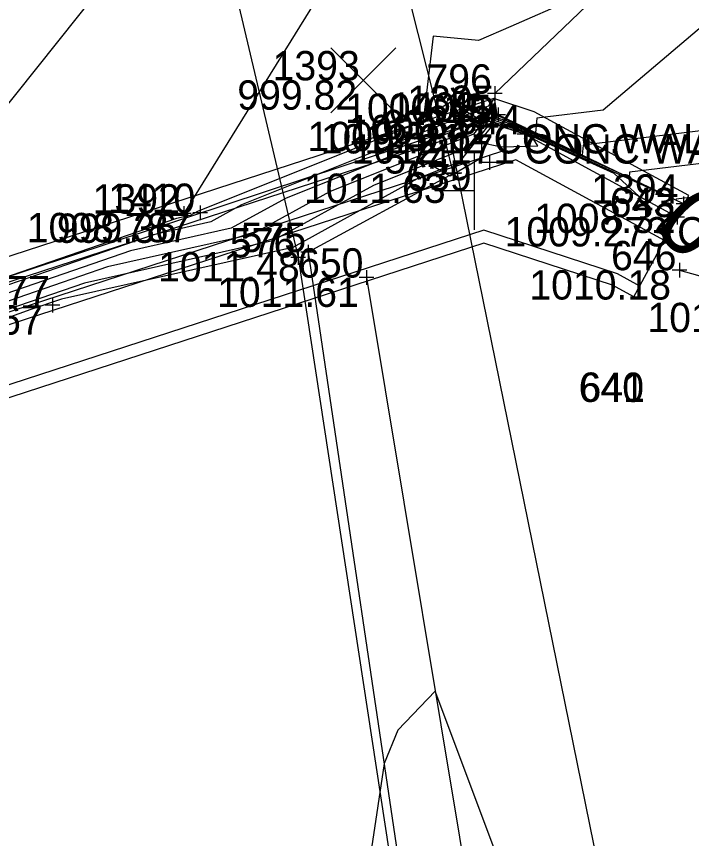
# Model space of a CAD drawing. Extents: x 2354693 to 2355622, y 637071 to 710080.
# Drawn here: x 2355356.22 to 2355383.87, y 709248.7 to 709282.34 of the extents above; entities that cross this region are included whole.
import ezdxf

# ---------------------------------------------------------------- set-up
doc = ezdxf.new("R2010")
doc.units = 0
for name, color, linetype in [('BR_X_Sub_Foot_Object', 7, 'Continuous'), ('BR_X_SV_Abut', 7, 'Continuous'), ('BR_X_SV_Beam_Seat', 7, 'Continuous'), ('DT_X_Contour_Major', 7, 'Continuous'), ('DT_X_Contour_Minor', 7, 'Continuous'), ('HY_X_Water_Edge', 7, 'Continuous'), ('PM_X_Surveyed_Line', 7, 'Continuous'), ('PV_X_EOP', 7, 'Continuous'), ('PV_X_Shoulder', 7, 'Continuous'), ('RD_X_Cells', 7, 'Continuous'), ('RD_X_GR_Lt', 7, 'Continuous'), ('SN_X_Public', 7, 'Continuous'), ('SV_X_Break_Lines', 7, 'Continuous'), ('SV_X_Random_Point', 7, 'Continuous'), ('SV_X_Shot_Marker', 7, 'Continuous'), ('SV_X_Text_Comment', 7, 'Continuous'), ('SV_X_Text_Elevation', 7, 'Continuous'), ('SV_X_Text_Name', 7, 'Continuous'), ('SV_X_Toe_of_Slope', 7, 'Continuous'), ('SV_X_Top_of_Bank', 7, 'Continuous')]:
    doc.layers.add(name, color=color, linetype=linetype)

msp = doc.modelspace()

# ---------------------------------------------------------------- linework, layer by layer
at = {"layer": 'BR_X_Sub_Foot_Object'}
for p, q in [((2355375.767, 709278.982), (2355343.344, 709268.433)), ((2355381.509, 709270.866), (2355383.755, 709275.004)), ((2355375.36, 709273.591), (2355346.408, 709264.172)), ((2355375.359, 709273.065), (2355346.73, 709263.751))]:
    msp.add_line(p, q, dxfattribs=at)
for points in [[(2355383.755, 709275.004), (2355377.429, 709278.438), (2355375.767, 709278.982)], [(2355381.747, 709271.305), (2355380.834, 709271.801), (2355375.36, 709273.591)], [(2355381.509, 709270.866), (2355380.635, 709271.34), (2355375.359, 709273.065)]]:
    msp.add_lwpolyline(points, dxfattribs=at)
at = {"layer": 'BR_X_SV_Abut'}
for p, q in [((2355375.766, 709277.93), (2355344.12, 709267.634)), ((2355376.127, 709276.82), (2355344.481, 709266.525)), ((2355376.68, 709276.474), (2355344.77, 709266.093))]:
    msp.add_line(p, q, dxfattribs=at)
for points in [[(2355383.278, 709274.125), (2355377.032, 709277.516), (2355375.766, 709277.93)], [(2355382.761, 709273.173), (2355376.68, 709276.474)]]:
    msp.add_lwpolyline(points, dxfattribs=at)
at = {"layer": 'BR_X_SV_Beam_Seat'}
for p, q in [((2355375.251, 709278.326), (2355375.251, 709277.726)), ((2355375.551, 709278.026), (2355374.951, 709278.026)), ((2355363.742, 709274.598), (2355363.742, 709273.998)), ((2355364.042, 709274.298), (2355363.442, 709274.298))]:
    msp.add_line(p, q, dxfattribs=at)
at = {"layer": 'DT_X_Contour_Major'}
for points in [[(2355412.935, 709323.858), (2355412.448, 709323.101), (2355399.508, 709300.34), (2355398.693, 709299.31), (2355397.28, 709297.832), (2355380.065, 709283.245), (2355378.962, 709283.026), (2355376.473, 709281.93), (2355375.148, 709281.346), (2355373.286, 709281.525), (2355372.881, 709278.048), (2355363.645, 709274.356), (2355363.341, 709274.189), (2355362.774, 709274.062), (2355345.265, 709268.035), (2355344.363, 709267.712), (2355344.138, 709267.795), (2355344.093, 709267.669), (2355343.399, 709266.464), (2355342.314, 709266.059), (2355339.268, 709265.779)], [(2355412.935, 709323.858), (2355412.448, 709323.101), (2355399.508, 709300.34), (2355398.693, 709299.31), (2355397.28, 709297.832), (2355380.065, 709283.245), (2355378.962, 709283.026), (2355376.473, 709281.93), (2355375.148, 709281.346), (2355373.286, 709281.525), (2355372.881, 709278.048), (2355363.645, 709274.356), (2355363.341, 709274.189), (2355362.774, 709274.062), (2355345.265, 709268.035), (2355344.363, 709267.712), (2355344.138, 709267.795), (2355344.093, 709267.669), (2355343.399, 709266.464), (2355342.314, 709266.059), (2355339.268, 709265.779)], [(2355382.151, 709274.282), (2355381.711, 709274.976), (2355380.703, 709275.914), (2355376.833, 709277.662), (2355375.801, 709278.001), (2355375.775, 709278.159), (2355374.352, 709276.373), (2355372.639, 709275.689), (2355367.547, 709272.887), (2355358.064, 709270.769), (2355356.817, 709270.34), (2355349.492, 709267.71), (2355349.176, 709262.706), (2355350.806, 709240.105), (2355350.736, 709238.617), (2355350.394, 709234.495), (2355350.966, 709223.924), (2355350.775, 709220.637), (2355349.098, 709206.498), (2355348.523, 709204.444)], [(2355382.151, 709274.282), (2355381.711, 709274.976), (2355380.703, 709275.914), (2355376.833, 709277.662), (2355375.801, 709278.001), (2355375.775, 709278.159), (2355374.352, 709276.373), (2355372.639, 709275.689), (2355367.547, 709272.887), (2355358.064, 709270.769), (2355356.817, 709270.34), (2355349.492, 709267.71), (2355349.176, 709262.706), (2355350.806, 709240.105), (2355350.736, 709238.617), (2355350.394, 709234.495), (2355350.966, 709223.924), (2355350.775, 709220.637), (2355349.098, 709206.498), (2355348.523, 709204.444)]]:
    msp.add_lwpolyline(points, dxfattribs=at)
at = {"layer": 'DT_X_Contour_Minor'}
for points in [[(2355395.378, 709291.328), (2355380.244, 709278.504), (2355377.533, 709278.175), (2355377.476, 709277.579), (2355376.098, 709278.202), (2355375.927, 709278.258), (2355375.806, 709278.989), (2355375.543, 709278.66), (2355365.444, 709274.623), (2355364.182, 709273.928), (2355361.832, 709273.404), (2355347.575, 709268.496), (2355344.823, 709267.508), (2355344.134, 709267.763), (2355343.996, 709267.379), (2355341.88, 709263.698), (2355341.299, 709263.481), (2355330.832, 709262.519), (2355327.686, 709262.765), (2355325.646, 709262.822), (2355317.774, 709259.038)], [(2355395.378, 709291.328), (2355380.244, 709278.504), (2355377.533, 709278.175), (2355377.476, 709277.579), (2355376.098, 709278.202), (2355375.927, 709278.258), (2355375.806, 709278.989), (2355375.543, 709278.66), (2355365.444, 709274.623), (2355364.182, 709273.928), (2355361.832, 709273.404), (2355347.575, 709268.496), (2355344.823, 709267.508), (2355344.134, 709267.763), (2355343.996, 709267.379), (2355341.88, 709263.698), (2355341.299, 709263.481), (2355330.832, 709262.519), (2355327.686, 709262.765), (2355325.646, 709262.822), (2355317.774, 709259.038)], [(2355403.537, 709290.84), (2355391.576, 709278.322), (2355390.037, 709277.018), (2355381.334, 709275.961), (2355381.313, 709275.742), (2355376.465, 709277.932), (2355375.864, 709278.129), (2355375.79, 709278.574), (2355374.947, 709277.517), (2355369.041, 709275.156), (2355365.864, 709273.408), (2355359.948, 709272.086), (2355352.196, 709269.418), (2355345.743, 709267.101), (2355344.127, 709267.698), (2355343.804, 709266.798), (2355341.172, 709262.22), (2355340.042, 709259.574), (2355339.274, 709259.634), (2355334.287, 709259.774), (2355315.044, 709250.525)], [(2355403.537, 709290.84), (2355391.576, 709278.322), (2355390.037, 709277.018), (2355381.334, 709275.961), (2355381.313, 709275.742), (2355376.465, 709277.932), (2355375.864, 709278.129), (2355375.79, 709278.574), (2355374.947, 709277.517), (2355369.041, 709275.156), (2355365.864, 709273.408), (2355359.948, 709272.086), (2355352.196, 709269.418), (2355345.743, 709267.101), (2355344.127, 709267.698), (2355343.804, 709266.798), (2355341.172, 709262.22), (2355340.042, 709259.574), (2355339.274, 709259.634), (2355334.287, 709259.774), (2355315.044, 709250.525)], [(2355393.477, 709284.825), (2355385.14, 709277.761), (2355379.434, 709277.068), (2355379.395, 709276.661), (2355376.282, 709278.067), (2355375.896, 709278.193), (2355375.798, 709278.782), (2355375.245, 709278.088), (2355367.243, 709274.889), (2355365.023, 709273.668), (2355360.89, 709272.745), (2355349.886, 709268.957), (2355345.283, 709267.305), (2355344.131, 709267.73), (2355343.9, 709267.089), (2355340.361, 709260.932), (2355340.284, 709260.903), (2355338.897, 709260.776), (2355333.48, 709261.199), (2355329.967, 709261.298), (2355316.409, 709254.782)], [(2355393.477, 709284.825), (2355385.14, 709277.761), (2355379.434, 709277.068), (2355379.395, 709276.661), (2355376.282, 709278.067), (2355375.896, 709278.193), (2355375.798, 709278.782), (2355375.245, 709278.088), (2355367.243, 709274.889), (2355365.023, 709273.668), (2355360.89, 709272.745), (2355349.886, 709268.957), (2355345.283, 709267.305), (2355344.131, 709267.73), (2355343.9, 709267.089), (2355340.361, 709260.932), (2355340.284, 709260.903), (2355338.897, 709260.776), (2355333.48, 709261.199), (2355329.967, 709261.298), (2355316.409, 709254.782)], [(2355384.85, 709275.05), (2355383.235, 709274.854), (2355383.232, 709274.823), (2355376.649, 709277.797), (2355375.833, 709278.065), (2355375.782, 709278.367), (2355374.649, 709276.945), (2355370.84, 709275.422), (2355366.705, 709273.148), (2355359.006, 709271.428), (2355354.506, 709269.879), (2355346.203, 709266.898), (2355344.124, 709267.666), (2355343.708, 709266.508), (2355342.404, 709264.24), (2355341.712, 709262.62), (2355342.07, 709261.383), (2355340.341, 709258.201), (2355338.608, 709258.25), (2355328.095, 709253.197), (2355324.733, 709239.533), (2355325.082, 709235.631), (2355314.187, 709221.342)], [(2355384.85, 709275.05), (2355383.235, 709274.854), (2355383.232, 709274.823), (2355376.649, 709277.797), (2355375.833, 709278.065), (2355375.782, 709278.367), (2355374.649, 709276.945), (2355370.84, 709275.422), (2355366.705, 709273.148), (2355359.006, 709271.428), (2355354.506, 709269.879), (2355346.203, 709266.898), (2355344.124, 709267.666), (2355343.708, 709266.508), (2355342.404, 709264.24), (2355341.712, 709262.62), (2355342.07, 709261.383), (2355340.341, 709258.201), (2355338.608, 709258.25), (2355328.095, 709253.197), (2355324.733, 709239.533), (2355325.082, 709235.631), (2355314.187, 709221.342)], [(2355375.767, 709277.952), (2355375.158, 709277.188), (2355376.101, 709277.003), (2355377.577, 709277.037), (2355377.4, 709277.316), (2355377.321, 709277.39), (2355377.016, 709277.528), (2355375.769, 709277.937), (2355375.767, 709277.952)], [(2355375.767, 709277.952), (2355375.158, 709277.188), (2355376.101, 709277.003), (2355377.577, 709277.037), (2355377.4, 709277.316), (2355377.321, 709277.39), (2355377.016, 709277.528), (2355375.769, 709277.937), (2355375.767, 709277.952)], [(2355388.382, 709181.549), (2355387.248, 709201.609), (2355389.188, 709218.85), (2355383.697, 709231.486), (2355379.499, 709244.29), (2355376.776, 709247.498), (2355376.105, 709247.453), (2355373.371, 709254.729), (2355371.839, 709253.134), (2355371.28, 709251.764), (2355370.025, 709243.384), (2355369.092, 709233.774), (2355367.481, 709217.574), (2355362.053, 709192.157), (2355358.45, 709172.035)], [(2355388.382, 709181.549), (2355387.248, 709201.609), (2355389.188, 709218.85), (2355383.697, 709231.486), (2355379.499, 709244.29), (2355376.776, 709247.498), (2355376.105, 709247.453), (2355373.371, 709254.729), (2355371.839, 709253.134), (2355371.28, 709251.764), (2355370.025, 709243.384), (2355369.092, 709233.774), (2355367.481, 709217.574), (2355362.053, 709192.157), (2355358.45, 709172.035)]]:
    msp.add_lwpolyline(points, dxfattribs=at)
at = {"layer": 'HY_X_Water_Edge'}
for points in [[(2355375.813, 709279.177), (2355398.044, 709300.445), (2355412.554, 709325.036), (2355426.374, 709348.201), (2355435.337, 709371.973), (2355446.496, 709387.253), (2355453.681, 709395.052)], [(2355338.241, 709293.806), (2355335.553, 709300.961), (2355309.837, 709289.282), (2355293.059, 709285.327), (2355275.057, 709268.764), (2355271.816, 709252.103), (2355293.45, 709267.257), (2355309.044, 709270.656), (2355323.015, 709269.316), (2355355.379, 709278.139), (2355366.295, 709291.81), (2355368.889, 709301.061)]]:
    msp.add_lwpolyline(points, dxfattribs=at)
at = {"layer": 'PM_X_Surveyed_Line'}
msp.add_lwpolyline([(2355180.148, 709561.237), (2355214.753, 709522.888), (2355249.307, 709484.271), (2355284.017, 709443.142), (2355315.552, 709399.77), (2355328.888, 709377.573), (2355342.967, 709349.789), (2355353.365, 709324.191), (2355361.351, 709299.648), (2355367.764, 709272.473), (2355372.191, 709243.487), (2355373.87, 709217.884), (2355371.213, 709164.414), (2355367.135, 709139.625), (2355360.061, 709111.877), (2355351.618, 709085.78), (2355342.505, 709062.338), (2355329.445, 709031.419), (2355320.624, 709012.583)], dxfattribs=at)
at = {"layer": 'PV_X_EOP'}
msp.add_lwpolyline([(2355180.814, 709561.741), (2355215.64, 709523.556), (2355249.922, 709484.356), (2355284.407, 709443.36), (2355315.939, 709399.966), (2355329.751, 709378.355), (2355343.524, 709350.098), (2355349.219, 709351.4), (2355359.304, 709326.795), (2355367.588, 709301.754), (2355374.108, 709275.907), (2355368.17, 709272.694), (2355372.498, 709243.563), (2355374.502, 709217.665), (2355371.414, 709164.432), (2355367.842, 709139.325), (2355361.02, 709111.642), (2355352.388, 709085.56), (2355343.445, 709061.967), (2355330.49, 709031.083), (2355321.141, 709011.801)], dxfattribs=at)
at = {"layer": 'PV_X_Shoulder'}
msp.add_lwpolyline([(2355370.563, 709271.651), (2355375.125, 709244.152), (2355376.457, 709217.439), (2355373.313, 709164.025), (2355369.833, 709138.826), (2355363.46, 709110.733), (2355354.734, 709084.843), (2355345.666, 709061.243), (2355332.683, 709029.848), (2355323.397, 709011.312)], dxfattribs=at)
at = {"layer": 'RD_X_Cells'}
msp.add_lwpolyline([(2355372.687, 709276.566), (2355373.985, 709275.816), (2355375.284, 709276.566), (2355375.284, 709278.066), (2355373.985, 709278.816), (2355372.687, 709278.066), (2355372.687, 709276.566)], dxfattribs=at)
at = {"layer": 'RD_X_GR_Lt'}
msp.add_lwpolyline([(2355373.985, 709277.316), (2355381.031, 709242.7), (2355383.592, 709226.419), (2355385.198, 709201.576), (2355387.106, 709175.345)], dxfattribs=at)
at = {"layer": 'SN_X_Public'}
for p, q in [((2355374.964, 709276.805), (2355374.964, 709273.605)), ((2355374.964, 709275.205), (2355373.364, 709275.205))]:
    msp.add_line(p, q, dxfattribs=at)
at = {"layer": 'SV_X_Break_Lines'}
msp.add_lwpolyline([(2355383.541, 709274.675), (2355375.952, 709278.309), (2355344.139, 709267.811), (2355340.129, 709260.509)], dxfattribs=at)
at = {"layer": 'SV_X_Random_Point'}
for p, q in [((2355369.097, 709278.387), (2355371.763, 709281.057)), ((2355369.097, 709281.057), (2355371.763, 709278.387))]:
    msp.add_line(p, q, dxfattribs=at)
at = {"layer": 'SV_X_Shot_Marker'}
for p, q in [((2355375.813, 709279.477), (2355375.813, 709278.877)), ((2355376.113, 709279.177), (2355375.513, 709279.177)), ((2355375.952, 709278.609), (2355375.952, 709278.009)), ((2355375.351, 709278.343), (2355375.351, 709277.743)), ((2355376.252, 709278.309), (2355375.652, 709278.309)), ((2355375.766, 709278.23), (2355375.766, 709277.63)), ((2355375.766, 709278.23), (2355375.766, 709277.63)), ((2355375.651, 709278.043), (2355375.051, 709278.043)), ((2355376.066, 709277.93), (2355375.466, 709277.93)), ((2355376.066, 709277.93), (2355375.466, 709277.93)), ((2355377.032, 709277.816), (2355377.032, 709277.216)), ((2355377.032, 709277.816), (2355377.032, 709277.216)), ((2355377.332, 709277.516), (2355376.732, 709277.516)), ((2355377.332, 709277.516), (2355376.732, 709277.516)), ((2355375.593, 709276.658), (2355375.593, 709276.058)), ((2355374.108, 709276.207), (2355374.108, 709275.606)), ((2355374.166, 709276.222), (2355374.166, 709275.622)), ((2355375.893, 709276.358), (2355375.293, 709276.358)), ((2355374.408, 709275.907), (2355373.808, 709275.907)), ((2355374.466, 709275.922), (2355373.866, 709275.922)), ((2355383.541, 709274.975), (2355383.541, 709274.375)), ((2355363.073, 709274.571), (2355363.073, 709273.971)), ((2355383.841, 709274.675), (2355383.241, 709274.675)), ((2355383.278, 709274.425), (2355383.278, 709273.825)), ((2355383.278, 709274.425), (2355383.278, 709273.825)), ((2355363.373, 709274.271), (2355362.774, 709274.271)), ((2355383.578, 709274.125), (2355382.978, 709274.125)), ((2355383.578, 709274.125), (2355382.978, 709274.125)), ((2355367.764, 709272.774), (2355367.764, 709272.173)), ((2355368.17, 709272.995), (2355368.17, 709272.394)), ((2355368.064, 709272.473), (2355367.464, 709272.473)), ((2355368.47, 709272.694), (2355367.87, 709272.694)), ((2355383.373, 709272.251), (2355383.373, 709271.651)), ((2355370.563, 709271.951), (2355370.563, 709271.351)), ((2355383.673, 709271.951), (2355383.073, 709271.951)), ((2355370.863, 709271.651), (2355370.263, 709271.651)), ((2355357.703, 709270.817), (2355357.703, 709270.217)), ((2355358.002, 709270.517), (2355357.403, 709270.517))]:
    msp.add_line(p, q, dxfattribs=at)
at = {"layer": 'SV_X_Toe_of_Slope'}
for points in [[(2355375.813, 709279.177), (2355398.044, 709300.445), (2355412.554, 709325.036), (2355426.374, 709348.201), (2355435.337, 709371.973), (2355446.496, 709387.253), (2355453.681, 709395.052)], [(2355338.248, 709293.892), (2355335.553, 709300.961), (2355309.837, 709289.282), (2355293.059, 709285.327), (2355275.057, 709268.764), (2355271.816, 709252.103), (2355293.45, 709267.257), (2355309.044, 709270.656), (2355323.015, 709269.316), (2355355.379, 709278.139), (2355366.295, 709291.81), (2355368.889, 709301.061)], [(2355374.931, 709286.841), (2355369.613, 709284.833), (2355363.073, 709274.271)]]:
    msp.add_lwpolyline(points, dxfattribs=at)
at = {"layer": 'SV_X_Top_of_Bank'}
msp.add_lwpolyline([(2355383.373, 709271.951), (2355388.183, 709270.618), (2355390.473, 709244.635), (2355393.018, 709219.275), (2355395.377, 709189.683)], dxfattribs=at)

# ---------------------------------------------------------------- texts
at = {"layer": 'BR_X_SV_Beam_Seat'}
for s, p in [('1409', (2355371.516, 709278.026)), ('1009.586', (2355368.143, 709276.826)), ('1410', (2355359.977, 709274.298)), ('1008.787', (2355356.647, 709273.098))]:
    msp.add_text(s, height=1.2, dxfattribs=at).set_placement(p)
at = {"layer": 'DT_X_Contour_Major'}
msp.add_text('1010', height=2.8, rotation=135.8804, dxfattribs=at).set_placement((2355390.174, 709269.854))
msp.add_text('1010', height=2.8, rotation=135.8804, dxfattribs=at).set_placement((2355390.174, 709269.854))
at = {"layer": 'SV_X_Text_Comment'}
for p in [(2355375.766, 709276.73), (2355377.032, 709276.316), (2355383.278, 709272.925)]:
    msp.add_text('CONC.WALL', height=1.2, dxfattribs=at).set_placement(p)
at = {"layer": 'SV_X_Text_Elevation'}
for s, p in [('999.82', (2355365.268, 709278.522)), ('1000.19', (2355369.684, 709277.977)), ('1000.41', (2355369.831, 709277.109)), ('1012.212', (2355368.689, 709276.73)), ('1012.171', (2355369.952, 709276.316)), ('1011.63', (2355367.999, 709274.707)), ('1008.32', (2355377.421, 709273.475)), ('999.36', (2355357.881, 709273.071)), ('1009.273', (2355376.211, 709272.925)), ('1011.48', (2355362.024, 709271.495)), ('1010.18', (2355377.227, 709270.751)), ('1011.61', (2355364.442, 709270.451)), ('1010.767', (2355350.607, 709269.317)), ('1010.31', (2355382.062, 709269.418))]:
    msp.add_text(s, height=1.2, dxfattribs=at).set_placement(p)
at = {"layer": 'SV_X_Text_Name'}
for s, p in [('1393', (2355366.714, 709279.722)), ('796', (2355373.014, 709279.177)), ('1395', (2355372.232, 709278.309)), ('645', (2355373.003, 709277.93)), ('638', (2355371.19, 709277.316)), ('644', (2355374.213, 709277.516)), ('574', (2355371.289, 709275.907)), ('639', (2355372.186, 709275.205)), ('1394', (2355379.764, 709274.675)), ('1392', (2355359.347, 709274.271)), ('643', (2355380.52, 709274.125)), ('575', (2355365.408, 709272.694)), ('576', (2355364.965, 709272.473)), ('646', (2355380.574, 709271.951)), ('650', (2355367.756, 709271.651)), ('577', (2355354.916, 709270.517)), ('640', (2355379.246, 709266.562)), ('641', (2355379.28, 709266.566))]:
    msp.add_text(s, height=1.2, dxfattribs=at).set_placement(p)

doc.saveas('drawing.dxf')
